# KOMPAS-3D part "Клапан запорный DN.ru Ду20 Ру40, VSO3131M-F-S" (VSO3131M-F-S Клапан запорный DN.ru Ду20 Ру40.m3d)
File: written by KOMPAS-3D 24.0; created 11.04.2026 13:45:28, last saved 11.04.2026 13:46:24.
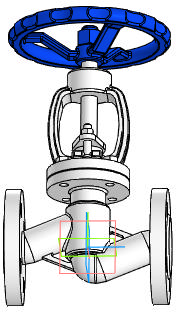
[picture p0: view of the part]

Document properties: Автор: R2D2; Полное имя файла: E:\Работа\Зайцев\VSO3131M-F-S Клапан запорный DN.ru Ду15-100 Ру40\DN20\VSO3131M-F-S Клапан запорный DN.ru Ду20 Ру40.m3d

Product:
- Part/product: Клапан запорный DN.ru Ду20 Ру40  | designation VSO3131M-F-S
    Масса: 5.15
    Раздел спецификации: Прочие изделия
    Примечание: D090-02138

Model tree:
1. Операция без истории:2

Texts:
  VSO3131M-F-S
